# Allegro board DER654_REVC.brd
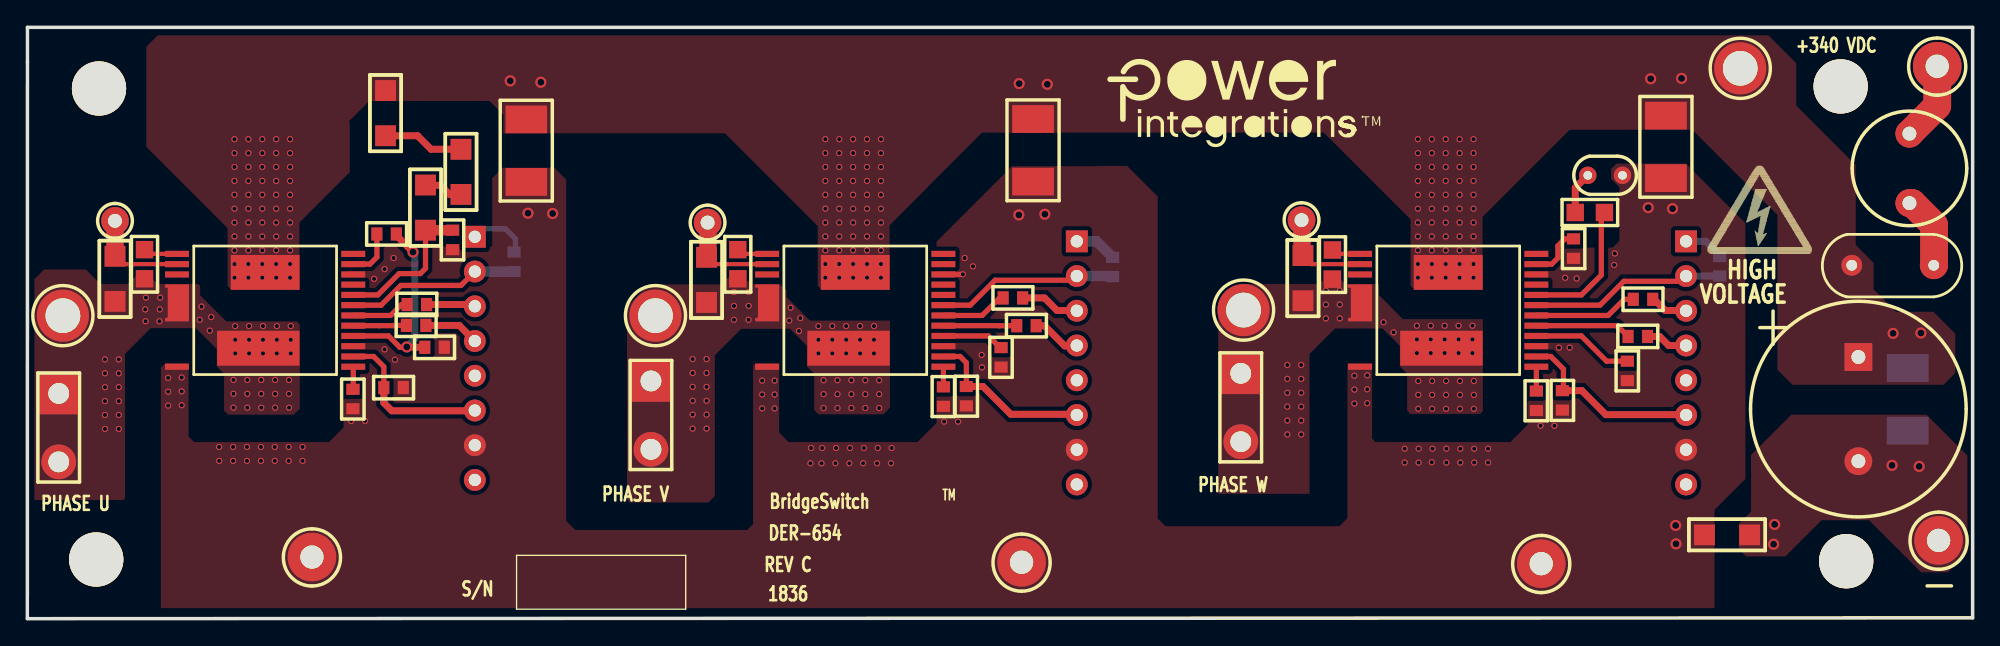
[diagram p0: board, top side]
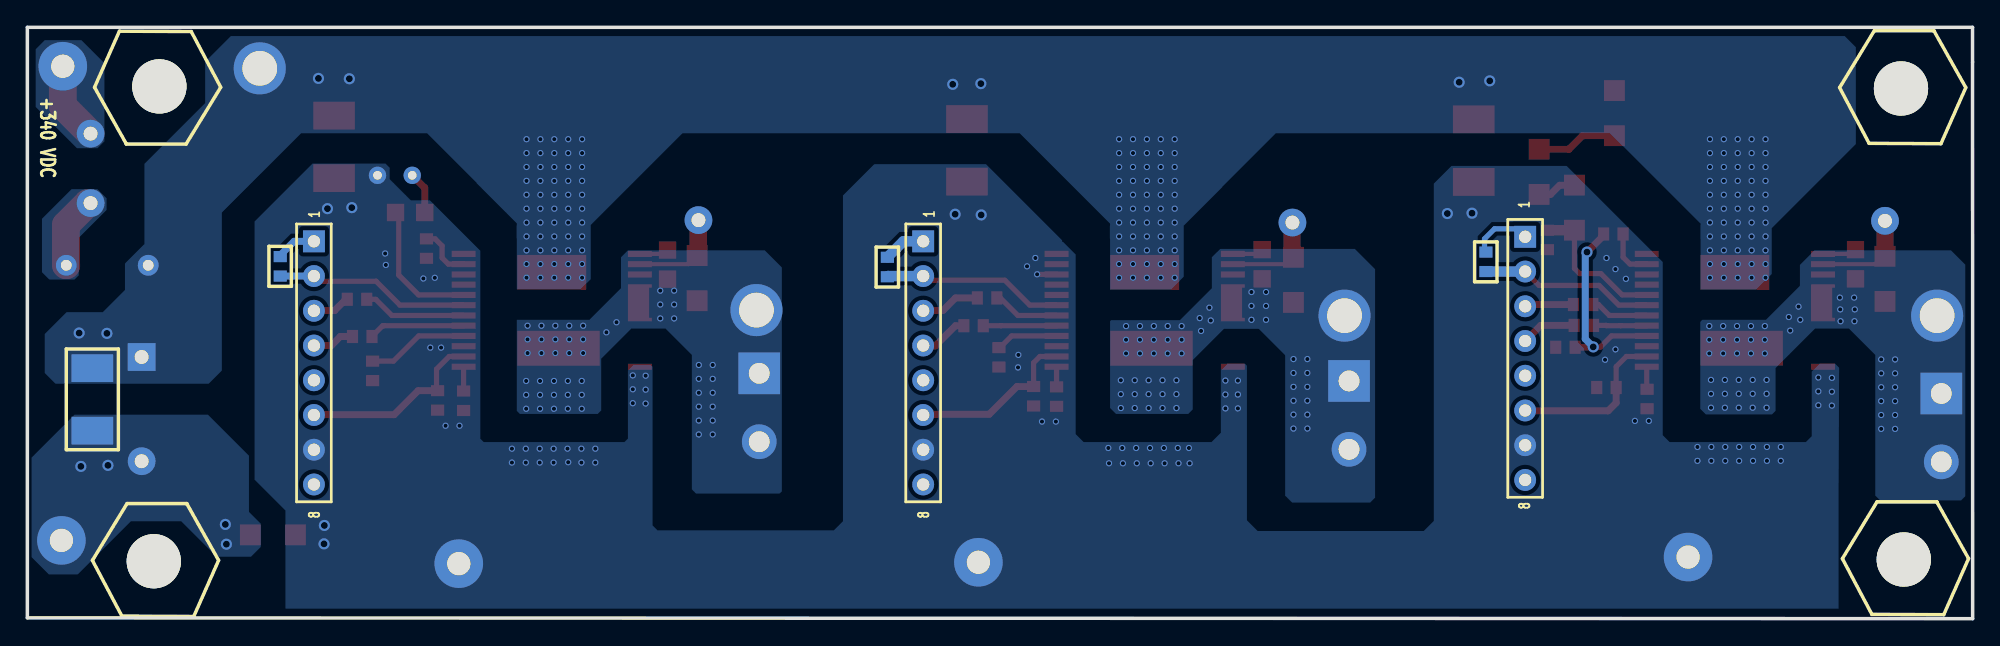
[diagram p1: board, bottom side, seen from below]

Outline 142.25 x 43.24 mm; copper layers: TOP, BOTTOM. Coordinates in mm from the lower left corner of the outline.
Outline path: 0,0 142.25,0.06 142.25,43.24 0.01,43.24 0.01,40.7 0,0

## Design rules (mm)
constraint set DEFAULT: min track width 0.508

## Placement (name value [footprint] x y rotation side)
C1  22 uF  [PIPOLCAPCLYD630LS300040]  133.89 19.13 270 top
C2  220 nF  [PISMC1812]  137.5 18.32 270 bottom
C3  220 nF  [PISMC1812]  36.48 36.51 270 top
C4  4.7 uF  [PISMC1206]  6.41 26.5 270 top
C5  100 pF  [PISMC0603]  31.1 28.4 270 top
C6  1 uF  [PISMC0603]  29.07 19.84 0 top
C7  220 nF  [PISMC1812]  73.54 36.53 270 top
C8  4.7 uF  [PISMC1206]  49.66 26.42 270 top
C9  1 uF  [PISMC0603]  71.2 19.82 270 top
C10  220 nF  [PISMC1812]  119.82 36.79 270 top
C11  4.7 uF  [PISMC1206]  93.28 26.55 270 top
C12  1 uF  [PISMC0603]  117 18.83 270 top
F1  3.15 A  [PI_TR5_SUBMIN_FUSE]  137.62 35.47 270 top
J1  CON8  [HDR1X8]  32.72 27.92 270 top
J2  CON8  [HDR1X8]  76.74 27.59 270 top
J3  CON8  [HDR1X8]  121.29 27.59 270 top
J4  CON2  [PI_CONN_QC_TAB_2PIN_LS200]  2.29 16.47 180 top
J5  CON2  [PI_CONN_QC_TAB_2PIN_LS200]  45.6 17.38 180 top
J6  CON2  [PI_CONN_QC_TAB_2PIN_LS200]  88.73 17.94 180 top
J7  CON1  [PI_KEYSTONE1514-2_POST]  125.25 40.24 0 top
J8  CON1  [PI_KEYSTONE1514-2_POST]  2.6 22.16 0 top
J9  CON1  [PI_KEYSTONE1514-2_POST]  45.93 22.16 0 top
J10  CON1  [PI_KEYSTONE1514-2_POST]  88.93 22.56 0 top
NOREF  -  []  0.01 0.06 90 top
NOREF#2  -  []  -143.92 73.77 0 top
NOREF#3  -  []  78.98 40.9 0 top
NOREF#4  -  []  -244.62 -165.09 0 top
NOREF#5  -  []  0.01 40.7 0 top
POST-CRKT_BRD_6-32_HEX1  Post Hex, 6-32, snap, 0.375L, NYL  [PIMTGHOLED156]  5.04 4.33 180 bottom
POST-CRKT_BRD_6-32_HEX2  Post Hex, 6-32, snap, 0.375L, NYL  [PIMTGHOLED156]  132.6 38.92 0 bottom
POST-CRKT_BRD_6-32_HEX3  Post Hex, 6-32, snap, 0.375L, NYL  [PIMTGHOLED156]  133 4.2 180 bottom
POST-CRKT_BRD_6-32_HEX4  Post Hex, 6-32, snap, 0.375L, NYL  [PIMTGHOLED156]  5.24 38.77 180 bottom
R1  10  [PISMR0603]  29.19 22.97 180 top
R2  10  [PISMR0603]  29.14 21.45 180 top
R3  3 M  [PISMR1206]  26.19 38.62 270 top
R4  2.00 M  [PISMR1206]  31.71 31.02 90 top
R5  2.00 M  [PISMR1206]  29.12 28.4 90 top
R6  10 k  [PISMR0603]  26.07 16.9 0 top
R7  0.0  [PISMR0603]  26.98 28.13 180 top
R8  44.2 k  [PISMR0603]  23.81 16.77 270 top
R9  44.2 k  [PISMR0805]  8.57 26.98 270 top
R10  10  [PISMR0603]  72.78 23.45 180 top
R11  10  [PISMR0603]  73.77 21.42 180 top
R12  10 k  [PISMR0603]  68.66 16.97 270 top
R13  44.2 k  [PISMR0603]  66.99 16.95 270 top
R14  44.2 k  [PISMR0805]  51.95 26.98 270 top
R15  10  [PISMR0603]  118.85 23.35 180 top
R16  10  [PISMR0603]  118.47 20.63 180 top
R17  4.75 k  [PISMR0805]  115.32 29.7 180 top
R18  10 k  [PISMR0603]  112.25 16.67 270 top
R19  0.0  [PISMR0603]  113.06 26.35 90 top
R20  44.2 k  [PISMR0603]  110.35 16.64 270 top
R21  44.2 k  [PISMR0805]  95.44 26.96 270 top
R22  4.7 k  [PISMR0603]  35.59 26.8 270 bottom
R23  4.7 k  [PISMR0603]  79.36 26.42 270 bottom
R24  4.7 k  [PISMR0603]  123.76 26.47 270 bottom
R25  0.0  [PISMR1206]  122.64 6.13 0 top
RT1  2.5  [PI_RAD180X395LS235D031]  139.4 25.84 180 top
RT2  100 k  [PI_RAD_118X118_LS100D025]  116.64 32.42 180 top
TP1  BLK  [PITPKEYSTONE125X125]  20.81 4.5 0 top
TP2  BLK  [PITPKEYSTONE125X125]  72.7 4.12 0 top
TP3  BLK  [PITPKEYSTONE125X125]  110.7 4.02 0 top
TP4  WHT  [PITPKEYSTONE100X100]  6.41 29.09 0 top
TP5  WHT  [PITPKEYSTONE100X100]  49.74 28.96 0 top
TP6  WHT  [PITPKEYSTONE100X100]  93.17 29.14 0 top
TP7  BLK  [PITPKEYSTONE125X125]  139.76 5.72 0 top
TP8  RED  [PITPKEYSTONE125X125]  139.66 40.39 0 top
U1  BRD1265C  [PI_IC_INSOP_24C]  23.83 18.42 180 top
U2  BRD1265C  [PI_IC_INSOP_24C]  66.99 18.42 180 top
U3  BRD1265C  [PI_IC_INSOP_24C]  110.35 18.42 180 top

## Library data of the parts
C1 = CAP POL: room: 1
C2 C3 C7 C10 = CAP NP: room: 1
C4 C8 C11 = CAP NP
C5 = CAP NP: room: 4
C6 C9 C12 = CAP NP: alternate symbols: (pismc0603_1); room: 4
F1 = FUSE: room: 1
J1-J3 = HEADER 8: room: 2
J4-J6 = CON2
J7 = TERM_1Pin: room: 1
J8 J10 = TERM_1Pin: room: 4
J9 = TERM_1Pin
POST-CRKT_BRD_6-32_HEX1-POST-CRKT_BRD_6-32_HEX4 = POST_CRKT_BRD_6-32_HEX
R1 R2 R6 R8-R25 = R
R3-R5 R7 = R: room: 4
RT1 = THERMISTOR: alternate symbols: (pirad550x410ls300040_h)
RT2 = THERMISTOR
TP1 TP7 TP8 = TESTPOINT: room: 4
TP2-TP6 = TESTPOINT
U1-U3 = BridgeSwitch

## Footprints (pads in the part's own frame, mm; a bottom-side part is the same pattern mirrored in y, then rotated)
HDR1X8
  rect 1.6x1.6 hole 0.899: 1(0,0)
  round 1.6 hole 0.899: 2(2.54,0) 3(5.08,0) 4(7.62,0) 5(10.16,0) 6(12.7,0) 7(15.24,0) 8(17.78,0)
PI_CONN_QC_TAB_2PIN_LS200
  rect 3.048x3.048 hole 1.524: 1(0,0)
  round 2.54 hole 1.524: 2(0,5.001)
PI_IC_INSOP_24C
  rect 1.75x0.45 smd: 1(0,0) 2(0,-0.749) 3(0,-1.501) 4(0,-2.25) 5(0,-3) 6(0,-3.749) 7(0,-4.501) 8(0,-5.25) 9(0,-6) 10(0,-6.749) 11(0,-7.501) 12(0,-8.25) 13(12.89,-8.25) 14(12.89,-7.501) 15(12.89,-6.749) 24(12.89,0)
  custom 0.437x0.437 smd: 16(12.89,-4.671)
  rect 6.03x2.555 smd: 19(6.939,-1.349)
  rect 5.039x2.545 smd: 25(6.444,-6.899)
PI_KEYSTONE1514-2_POST
  round 3.81 hole 2.54: 1(0,0)
PI_RAD180X395LS235D031
  round 1.524 hole 0.787: 1(0,0) 2(5.994,0)
PI_RAD_118X118_LS100D025
  round 1.27 hole 0.635: 1(0,0) 2(2.54,0)
PI_TR5_SUBMIN_FUSE
  round 2.032 hole 1.016: 1(0,0) 2(5.08,0)
PIMTGHOLED156
  round 3.962 hole 3.962: 1(0,0)
PIPOLCAPCLYD630LS300040
  rect 2.032x2.032 hole 1.016: 1(0,0)
  round 2.032 hole 1.016: 2(7.62,0)
PISMC0603
  rect 0.813x0.965 smd: 1(0,0) 2(1.422,0)
PISMC1206
  rect 1.524x1.524 smd: 1(0,0) 2(3.302,0)
PISMC1812
  rect 2.032x3.048 smd: 1(0,0) 2(4.572,0)
PISMR0603
  rect 0.813x0.965 smd: 1(0,0) 2(1.422,0)
PISMR0805
  rect 1.27x1.27 smd: 1(0,0) 2(2.134,0)
PISMR1206
  rect 1.524x1.524 smd: 1(0,0) 2(3.302,0)
PITPKEYSTONE100X100
  round 2.032 hole 1.016: 1(0,0)
PITPKEYSTONE125X125
  round 3.556 hole 1.702: 1(0,0)

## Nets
GND: C3.2 C5.2 C6.2 C7.2 C9.2 C10.2 C12.2 J1.7 J2.7 J3.7 R6.2 R8.2 R12.2 R13.2 R18.2 R19.1 R20.2 R25.1 RT2.1 TP1.1 TP2.1 TP3.1 U1.3 U1.10 U1.24 U2.3 U2.10 U2.24 U3.3 U3.10 U3.24
VDD_U: J1.1 R22.1
VDD_V: J2.1 R23.1
VDD_W: J3.1 R24.1
BPH_V: C8.1 TP5.1 U2.14
BPL_V: C9.1 U2.4
BPL_W: C12.1 U3.4
DCNEG: C1.2 C2.2 R25.2 TP7.1
DCPLUS: C1.1 C2.1 C3.1 C7.1 C10.1 J7.1 R3.1 RT1.2 U1.25 U2.25 U3.25
FAULT_U: J1.2 R22.2 U1.7
FAULT_V: J2.2 R23.2 U2.7
FAULT_W: J3.2 R24.2 U3.7
ID_U: R7.2 U1.11
ID_V: U2.11
ID_W: R19.2 U3.11
INH_U: R1.2 U1.6
INH_V: R10.2 U2.6
INH_W: R15.2 U3.6
INL_V: R11.2 U2.5
INL_W: R16.2 U3.5
IPH_U: J1.6 R6.1 U1.2
IPH_V: J2.6 R12.1 U2.2
IPH_W: J3.6 R18.1 U3.2
PHASE U: C4.2 J4.1 J4.2 J8.1 R9.2 U1.16 U1.19
PHASE V: C8.2 J5.1 J5.2 J9.1 R14.2 U2.16 U2.19
PHASE W: C11.2 J6.1 J6.2 J10.1 R21.2 U3.16 U3.19
POWER+: F1.1 TP8.1
PWMH_U: J1.3 R1.1
PWMH_V: J2.3 R10.1
PWMH_W: J3.3 R15.1
PWML_U: J1.4 R2.1
PWML_V: J2.4 R11.1
PWML_W: J3.4 R16.1
SM_U: C5.1 R5.1 U1.8
SM_V: U2.8
SM_W: R17.1 U3.8
XH_U: R9.1 U1.13
XH_V: R14.1 U2.13
XH_W: R21.1 U3.13
XL_U: R8.1 U1.1(XL)
XL_V: R13.1 U2.1(XL)
XL_W: R20.1 U3.1(XL)
N17053801: R3.2 R4.2
N17053803: R4.1 R5.2
N17056296: C4.1 TP4.1 U1.14
N17067195: C11.1 TP6.1 U3.14
N17109437: R17.2 RT2.2
N17176096: F1.2 RT1.1
N17218688: R2.2 U1.5
N17224134: C6.1 R7.1 U1.4

Pads without a net: J1 5 8; J2 5 8; J3 5 8; POST-CRKT_BRD_6-32_HEX1 1; POST-CRKT_BRD_6-32_HEX2 1; POST-CRKT_BRD_6-32_HEX3 1; POST-CRKT_BRD_6-32_HEX4 1; U1 9 12 15; U2 9 12 15; U3 9 12 15

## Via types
v1: diameter 0.813, hole 0.508, TOP to BOTTOM, 22 vias
v2: diameter 0.457, hole 0.305, TOP to BOTTOM, 401 vias

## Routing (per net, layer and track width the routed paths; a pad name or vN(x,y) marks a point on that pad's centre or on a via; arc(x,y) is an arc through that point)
GND: length 1.3
  TOP w0.381: U2.10 68.25,25.17 68.26,25.18
  vias: v1(36.61,29.65) v1(38.41,29.62) v1(72.5,29.52) v1(74.4,29.57) v1(118.52,30.06) v1(120.3,29.98) v1(120.53,6.81) v1(120.56,5.47) v2(10.29,17.61) v2(10.29,16.59) v2(10.29,15.58) v2(11.29,17.64) v2(11.29,16.62) v2(11.29,15.6) v2(14.03,12.56) v2(14.03,11.54) v2(15.04,12.56) v2(15.04,11.54) v2(16.06,12.56) v2(16.06,11.54) v2(17.08,12.56) v2(17.08,11.54) v2(18.09,12.56) v2(18.09,11.54) v2(19.11,12.56) v2(19.11,11.54) v2(20.12,12.56) v2(20.12,11.54) v2(23.68,14.46) v2(24.7,14.46) v2(25.36,24.85) v2(26.12,25.56) v2(26.12,19.69) v2(26.78,26.37) v2(26.88,18.93) v2(53.73,17.41) v2(53.73,16.39) v2(53.73,15.37) v2(54.64,17.41) v2(54.64,16.39) v2(54.64,15.37) v2(57.31,12.48) v2(57.26,11.36) v2(58.12,12.48) v2(58.07,11.36) v2(59.14,12.48) v2(59.09,11.36) v2(60.15,12.48) v2(60.1,11.36) v2(61.12,11.36) v2(61.17,12.48) v2(62.14,11.36) v2(62.19,12.48) v2(63.15,11.36) v2(63.2,12.48) v2(67.04,14.41) v2(68.05,14.41) v2(68.41,25.18) v2(68.54,26.37) v2(69.15,25.76) v2(69.78,19.29) v2(69.81,18.37) v2(97.04,17.76) v2(97.04,16.75) v2(97.04,15.73) v2(97.98,17.79) v2(97.98,16.77) v2(97.98,15.76) v2(100.72,12.43) v2(100.72,11.41) v2(101.73,12.43) v2(101.73,11.41) v2(102.75,12.43) v2(102.7,11.44) v2(103.77,12.43) v2(103.77,11.41) v2(104.78,12.43) v2(104.78,11.41) v2(105.8,12.43) v2(105.8,11.41) v2(106.81,12.43) v2(106.81,11.41) v2(110.65,14.1) v2(111.67,14.1) v2(112,19.82) v2(112.45,24.92) v2(112.78,19.82) v2(113.29,24.87) v2(116.03,25.86) v2(116.09,26.7)
VDD_U: length 4.5
  BOTTOM w0.381: R22.1 35.69,26.91 35.69,27.77 34.96,28.51 33.43,28.51 32.85,27.92 J1.1
VDD_V: length 3.1
  BOTTOM w0.762: R23.1 78.19,27.59 J2.1
VDD_W: length 3
  BOTTOM w0.508: J3.1 122.74,27.59 123.76,26.58 R24.1
BPH_V: length 7.3
  TOP w0.305: C8.1 49.66,26.23 49.97,25.92 U2.14
  TOP w1.27: C8.1 49.77,26.53 49.77,28.94 TP5.1
BPL_V: length 4.6
  TOP w0.381: U2.4 70.27,20.67 71.13,19.82
  TOP w0.508: 71.13,19.82 C9.1
BPL_W: length 7.4
  TOP w0.381: C12.1 115.48,18.83 113.63,20.67 U3.4
DCNEG:
  vias: v1(127.69,5.44) v1(127.77,6.89) v1(136.35,11.21) v1(138.34,11.13)
DCPLUS:
  vias: v1(35.31,39.33) v1(37.55,39.23) v1(72.52,39.12) v1(74.58,39.07) v1(118.7,39.48) v1(120.96,39.5) v1(136.43,20.86) v1(138.46,20.89) v2(15.15,35.06) v2(15.15,34.04) v2(15.15,33.03) v2(15.15,32.01) v2(15.15,31) v2(15.15,29.98) v2(15.15,28.96) v2(15.15,27.95) v2(15.15,26.93) v2(15.15,25.93) v2(15.15,24.93) v2(16.16,35.06) v2(16.16,34.04) v2(16.16,33.03) v2(16.16,32.01) v2(16.16,31) v2(16.16,29.98) v2(16.16,28.96) v2(16.16,27.95) v2(16.16,26.93) v2(16.16,25.93) v2(16.16,24.93) v2(17.18,35.06) v2(17.18,34.04) v2(17.18,33.03) v2(17.18,32.01) v2(17.18,31) v2(17.18,29.98) v2(17.18,28.96) v2(17.18,27.95) v2(17.18,26.93) v2(17.18,25.93) v2(17.18,24.93) v2(18.19,35.06) v2(18.19,34.04) v2(18.19,33.03) v2(18.19,32.01) v2(18.19,31) v2(18.19,29.98) v2(18.19,28.96) v2(18.19,27.95) v2(18.19,26.93) v2(18.19,25.93) v2(18.19,24.93) v2(19.21,35.06) v2(19.21,34.04) v2(19.21,33.03) v2(19.21,32.01) v2(19.21,31) v2(19.21,29.98) v2(19.21,28.96) v2(19.21,27.95) v2(19.21,26.93) v2(19.21,25.93) v2(19.21,24.93) v2(58.35,35.06) v2(58.35,34.04) v2(58.35,33.03) v2(58.35,32.01) v2(58.35,31) v2(58.35,29.98) v2(58.35,28.96) v2(58.35,27.95) v2(58.35,26.93) v2(58.35,25.93) v2(58.35,24.93) v2(59.37,35.06) v2(59.37,34.04) v2(59.37,33.03) v2(59.37,32.01) v2(59.37,31) v2(59.37,29.98) v2(59.37,28.96) v2(59.37,27.95) v2(59.37,26.93) v2(59.37,25.93) v2(59.37,24.93) v2(60.38,35.06) v2(60.38,34.04) v2(60.38,33.03) v2(60.38,32.01) v2(60.38,31) v2(60.38,29.98) v2(60.38,28.96) v2(60.38,27.95) v2(60.38,26.93) v2(60.38,25.93) v2(60.38,24.93) v2(61.4,35.06) v2(61.4,34.04) v2(61.4,33.03) v2(61.4,32.01) v2(61.4,31) v2(61.4,29.98) v2(61.4,28.96) v2(61.4,27.95) v2(61.4,26.93) v2(61.4,25.93) v2(61.4,24.93) v2(62.42,35.06) v2(62.42,34.04) v2(62.42,33.03) v2(62.42,32.01) v2(62.42,31) v2(62.42,29.98) v2(62.42,28.96) v2(62.42,27.95) v2(62.42,26.93) v2(62.42,25.93) v2(62.42,24.93) v2(101.68,35.06) v2(101.68,34.04) v2(101.68,33.03) v2(101.68,32.01) v2(101.68,31) v2(101.68,29.98) v2(101.68,28.96) v2(101.68,27.95) v2(101.68,26.93) v2(101.68,25.93) v2(101.68,24.93) v2(102.7,35.06) v2(102.7,34.04) v2(102.7,33.03) v2(102.7,32.01) v2(102.7,31) v2(102.7,29.98) v2(102.7,28.96) v2(102.7,27.95) v2(102.7,26.93) v2(102.7,25.93) v2(102.7,24.93) v2(103.72,35.06) v2(103.72,34.04) v2(103.72,33.03) v2(103.72,32.01) v2(103.72,31) v2(103.72,29.98) v2(103.72,28.96) v2(103.72,27.95) v2(103.72,26.93) v2(103.72,25.93) v2(103.72,24.93) v2(104.73,35.06) v2(104.73,34.04) v2(104.73,33.03) v2(104.73,32.01) v2(104.73,31) v2(104.73,29.98) v2(104.73,28.96) v2(104.73,27.95) v2(104.73,26.93) v2(104.73,25.93) v2(104.73,24.93) v2(105.75,35.06) v2(105.75,34.04) v2(105.75,33.03) v2(105.75,32.01) v2(105.75,31) v2(105.75,29.98) v2(105.75,28.96) v2(105.75,27.95) v2(105.75,26.93) v2(105.75,25.93) v2(105.75,24.93)
FAULT_U: length 12.8
  TOP w0.381: J1.2 31.71,24.37 27.31,24.37 25.87,22.92 U1.7
  BOTTOM w0.762: R22.2 J1.2
FAULT_V: length 13.3
  TOP w0.381: U2.7 68.95,22.92 70.77,24.75 76.44,24.75 J2.2
  BOTTOM w0.762: J2.2 79.31,25.05 R23.2
FAULT_W: length 14.3
  TOP w0.381: J3.2 120.91,24.67 116.75,24.67 115,22.92 U3.7
  BOTTOM w0.508: R24.2 J3.2
ID_U: length 3.6
  TOP w0.381: U1.11 25.05,25.92 25.56,26.43 R7.2
ID_W: length 4
  TOP w0.381: U3.11 111.46,25.92 111.92,26.38 111.92,27.26 112.43,27.77 R19.2
INH_U: length 4.3
  TOP w0.381: R1.2 27.36,22.97 26.57,22.17 U1.6
INH_V: length 4.9
  TOP w0.381: U2.6 69.82,22.17 71.1,23.45 R10.2
INH_W: length 7.6
  TOP w0.381: R15.2 116.77,23.35 115.59,22.17 U3.6
INL_V: length 5.4
  TOP w0.381: U2.5 71.05,21.42 71.06,21.42 R11.2
INL_W: length 7
  TOP w0.381: U3.5 116.18,21.42 116.19,21.42 116.26,21.42 R16.2
IPH_U: length 12.1
  TOP w0.381: R6.1 26.07,18.42 25.32,19.17 U1.2
  TOP w0.508: J1.6 32.7,15.2 26.65,15.2 26.07,15.78 R6.1
IPH_V: length 12.5
  TOP w0.381: U2.2 68.21,19.17 68.66,18.71 R12.1
  TOP w0.508: J2.6 76.69,14.94 71.91,14.94 69.88,16.97 R12.1
IPH_W: length 13.8
  TOP w0.381: U3.2 111.4,19.17 112.33,18.24 112.33,16.75 R18.1
  TOP w0.508: J3.6 121.27,14.92 115.43,14.92 113.67,16.67 R18.1
PHASE U:
  vias: v2(5.67,18.96) v2(5.67,17.94) v2(5.67,16.92) v2(5.67,15.91) v2(5.67,14.89) v2(5.67,13.88) v2(6.69,18.96) v2(6.69,17.94) v2(6.69,16.92) v2(6.69,15.91) v2(6.69,14.89) v2(6.69,13.88) v2(8.62,22.61) v2(8.64,21.75) v2(8.67,23.48) v2(9.71,23.48) v2(9.68,22.61) v2(9.66,21.75) v2(12.61,21.85) v2(12.73,22.82) v2(13.34,21.06) v2(13.44,22.05) v2(15.07,17.46) v2(15.07,16.44) v2(15.07,15.43) v2(15.2,21.39) v2(15.2,20.39) v2(15.2,19.39) v2(16.09,17.46) v2(16.09,16.44) v2(16.09,15.43) v2(16.21,21.39) v2(16.21,20.39) v2(16.21,19.39) v2(17.1,17.46) v2(17.1,16.44) v2(17.1,15.43) v2(17.23,21.39) v2(17.23,20.39) v2(17.23,19.39) v2(18.12,17.46) v2(18.12,16.44) v2(18.12,15.43) v2(18.24,21.39) v2(18.24,20.39) v2(18.24,19.39) v2(19.13,17.46) v2(19.13,16.44) v2(19.13,15.43) v2(19.26,21.39) v2(19.26,20.39) v2(19.26,19.39)
PHASE V:
  vias: v2(48.65,18.98) v2(48.65,17.97) v2(48.65,16.95) v2(48.65,15.93) v2(48.65,14.92) v2(48.65,13.9) v2(49.66,18.98) v2(49.66,17.97) v2(49.66,16.95) v2(49.66,15.93) v2(49.66,14.92) v2(49.66,13.9) v2(51.67,23.88) v2(51.67,22.87) v2(51.67,21.85) v2(52.74,23.88) v2(52.74,22.87) v2(52.74,21.85) v2(55.71,21.8) v2(55.81,22.74) v2(56.42,21.04) v2(56.52,21.98) v2(57.84,21.39) v2(57.84,20.39) v2(57.84,19.39) v2(58.22,17.43) v2(58.22,16.42) v2(58.22,15.4) v2(58.86,21.39) v2(58.86,20.39) v2(58.86,19.39) v2(59.24,17.43) v2(59.24,16.42) v2(59.24,15.4) v2(59.88,21.39) v2(59.88,20.39) v2(59.88,19.39) v2(60.26,17.43) v2(60.26,16.42) v2(60.26,15.4) v2(60.89,21.39) v2(60.89,20.39) v2(60.89,19.39) v2(61.27,17.43) v2(61.27,16.42) v2(61.27,15.4) v2(61.91,21.39) v2(61.91,20.39) v2(61.91,19.39) v2(62.29,17.43) v2(62.29,16.42) v2(62.29,15.4)
PHASE W:
  vias: v2(92.13,18.55) v2(92.13,17.53) v2(92.13,16.52) v2(92.13,15.5) v2(92.13,14.49) v2(92.13,13.47) v2(93.15,18.55) v2(93.15,17.53) v2(93.15,16.52) v2(93.15,15.5) v2(93.15,14.49) v2(93.15,13.47) v2(94.95,23.99) v2(94.95,22.97) v2(94.95,21.95) v2(95.97,23.99) v2(95.97,22.97) v2(95.97,21.95) v2(99.17,21.67) v2(99.91,20.94) v2(101.61,21.42) v2(101.61,20.42) v2(101.61,19.42) v2(101.71,17.38) v2(101.71,16.37) v2(101.71,15.35) v2(102.62,21.42) v2(102.62,20.42) v2(102.62,19.42) v2(102.73,17.38) v2(102.73,16.37) v2(102.73,15.35) v2(103.64,21.42) v2(103.64,20.42) v2(103.64,19.42) v2(103.74,17.38) v2(103.74,16.37) v2(103.74,15.35) v2(104.66,21.42) v2(104.66,20.42) v2(104.66,19.42) v2(104.76,17.38) v2(104.76,16.37) v2(104.76,15.35) v2(105.67,21.42) v2(105.67,20.42) v2(105.67,19.42) v2(105.77,17.38) v2(105.77,16.37) v2(105.77,15.35)
POWER+: length 5.8
  TOP w2.032: F1.1 139.66,37.5 TP8.1
PWMH_U: length 3.6
  TOP w0.508: R1.1 32.6,22.97 J1.3
PWMH_V: length 4.4
  TOP w0.508: R10.1 74.38,23.45 75.29,22.54 76.72,22.54 J2.3
PWMH_W: length 2.8
  TOP w0.508: R15.1 118.96,23.35 119.77,22.54 121.27,22.54 J3.3
PWML_U: length 4.1
  TOP w0.508: J1.4 31.58,21.45 R2.1
PWML_V: length 3.6
  TOP w0.508: J2.4 76.72,19.95 75.85,19.95 74.38,21.42 R11.1
PWML_W: length 3.1
  TOP w0.508: R16.1 119.36,20.63 120.02,19.97 J3.4
SM_U: length 10.9
  TOP w0.381: R5.1 29.12,25.61 28.73,25.23 27.19,25.23 25.63,23.67 U1.8
  TOP w0.762: C5.1 R5.1
SM_W: length 10
  TOP w0.381: U3.8 113.64,23.67 115.09,25.13 115.09,29.47 R17.1
XH_U: length 2.5
  TOP w0.305: R9.1 8.88,26.67 U1.13
XH_V: length 2.3
  TOP w0.305: R14.1 52.26,26.67 U2.13
XH_W: length 2.1
  TOP w0.305: U3.13 95.75,26.67 95.46,26.96 R21.1
XL_U: length 1.7
  TOP w0.381: R8.1 23.83,16.8 U1.1
XL_V: length 1.5
  TOP w0.381: R13.1 U2.1
XL_W: length 1.8
  TOP w0.381: R20.1 U3.1
N17053801: length 5.9
  TOP w0.508: R4.2 29.52,34.32 28.53,35.31 R3.2
N17053803: length 2.9
  TOP w0.508: R4.1 30.87,31.02 30.2,31.69 29.13,31.69 R5.2
N17056296: length 7.4
  TOP w0.305: C4.1 6.56,26.5 7.14,25.92 U1.14
  TOP w1.27: TP4.1 C4.1
N17067195: length 7.1
  TOP w0.305: U3.14 93.9,25.92 C11.1
  TOP w1.27: TP6.1 93.2,29.12 93.2,26.63 C11.1
N17109437: length 3.1
  TOP w0.508: R17.2 113.19,31.5 RT2.2
N17176096: length 5.4
  TOP w2.032: F1.2 137.83,30.39 139.43,28.79 139.43,25.86 RT1.1
N17218688: length 3.9
  TOP w0.381: U1.5 25.74,21.42 25.74,21.42 26.78,21.42 26.8,21.45 R2.2
N17224134: length 14.7
  TOP w0.381: 27.77,19.84 27.24,19.84 26.41,20.67 U1.4
  TOP w0.508: v1(28.2,26.8) 26.98,28.02 R7.1 ; v1(27.74,19.87) 27.77,19.84 C6.1 29.04,19.82
  BOTTOM w0.508: v1(28.2,26.8) 28.33,26.68 28.33,20.45 v1(27.74,19.87)

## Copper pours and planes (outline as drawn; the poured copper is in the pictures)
GND on TOP: 9.76,18.35 10.07,18.65 11.77,18.65 11.79,18.63 11.79,13.32 12.2,12.91 22.05,12.91 23.12,13.98 23.12,25.06 23.45,25.39 24.38,25.39 26.19,27.21 33.94,27.21 33.99,27.26 33.99,32.21 34.75,32.98 38.54,32.98 39.4,32.11 39.4,7.14 40.06,6.48 52.64,6.48 53.07,6.92 53.07,18.5 53.22,18.65 54.97,18.65 54.97,13.6 55.66,12.91 65.08,12.91 66.48,14.31 66.48,27.57 72,33.09 78.25,33.09 78.26,33.1 80.42,33.1 82.66,30.87 82.66,7.32 83.22,6.76 95.94,6.76 96.53,7.35 96.53,18.65 98.33,18.65 98.33,13.16 98.58,12.91 108.44,12.91 109.71,14.18 109.7,14.19 109.7,25.65 111.18,27.13 115.93,27.13 116.42,27.62 116.42,31.55 115.81,32.16 115.81,32.88 116.21,33.28 121.27,33.28 125.64,28.91 125.64,10.22 123.38,7.96 123.38,0.77 9.81,0.77 9.76,0.82
GND on BOTTOM: 9.8,9.91 9.76,18.35 10.07,18.65 11.18,18.65 11.77,18.07 11.77,13.34 12.2,12.91 22.16,12.91 22.66,13.42 22.66,26.08 29.69,33.1 38.11,33.1 39.4,31.81 39.4,7.14 40.14,6.41 52.28,6.41 53.07,7.2 53.07,18.5 53.26,18.69 53.26,18.66 53.25,18.65 54.49,18.65 54.97,18.17 54.97,13.6 55.66,12.91 65.01,12.91 65.59,13.49 65.59,26.63 66.52,27.55 66.58,27.55 66.58,27.67 72.14,33.23 80.32,33.23 82.61,30.94 82.61,7.12 83.27,6.46 96.17,6.46 96.53,6.81 96.53,18.42 96.68,18.57 97.9,18.57 98.33,18.14 98.33,13.16 98.58,12.91 108.87,12.91 109.13,13.16 109.13,26.91 112.81,30.59 114.21,30.59 115.76,32.14 115.76,32.93 115.73,32.95 116.06,33.28 121.39,33.28 125.64,29.04 125.64,10.17 123.38,7.91 123.38,0.73 9.8,0.73 9.8,9.9
DCNEG on TOP: 141.87,4.83 140.42,3.39 138.49,3.39 134.68,7.2 131.2,7.2 128.56,4.55 125.69,4.55 125.15,5.09 125.15,6.94 126.04,7.83 126.04,11.97 128.99,14.92 138.87,14.92 141.87,11.92
DCNEG on BOTTOM: 138.79,14.92 141.94,11.77 141.94,4.5 140.67,3.23 138.56,3.23 134.68,7.12 131,7.12 128.4,4.53 125.89,4.53 125.18,5.24 125.18,6.94 126.04,7.81 126.04,11.92 129.04,14.92
DCPLUS on TOP: 121.7,35.8 121.65,35.75 112.78,35.75 106.41,29.37 106.41,24.06 101.43,24.06 101.15,24.34 101.15,29.19 94.8,35.54 69.81,35.54 65.86,31.59 65.86,31.57 63.05,28.76 63.05,24.06 58.07,24.06 57.79,24.34 57.79,28.71 51.01,35.49 34.81,35.49 34.81,36.84 33.79,37.85 25,37.85 23.5,36.35 23.58,36.28 23.58,32.65 19.9,28.96 19.9,24.06 14.92,24.06 14.64,24.34 14.64,28.56 8.69,34.5 8.69,41.82 9.53,42.65 127.31,42.65 129.34,40.62 129.34,37.52 133.7,33.17 133.7,27.33 135.01,26.02 135.01,24.09 136.66,22.44 139.38,22.44 140.98,20.84 140.98,17.97 140.11,17.1 129.06,17.1 127.97,18.19 127.97,29.52
DCPLUS on BOTTOM: 128.99,17.18 128.02,18.14 128.02,29.7 122.23,35.49 113.01,35.49 109.41,31.88 109.41,31.86 106.46,28.91 106.46,28.79 106.47,28.77 106.47,27.81 106.46,27.8 106.46,24.09 101.79,24.09 101.05,24.82 101.05,28.79 94.34,35.49 69.68,35.49 63.08,28.89 63.08,28.76 63.09,28.75 63.09,27.78 63.08,27.77 63.08,24.06 58.63,24.06 57.69,25 57.69,28.73 54.87,31.55 54.87,31.58 50.96,35.49 26.5,35.49 19.9,28.89 19.9,28.76 19.91,28.75 19.91,27.78 19.9,27.77 19.9,24.06 15.83,24.06 14.69,25.2 14.69,28.56 8.54,34.7 8.54,41.79 9.35,42.6 127.36,42.6 129.24,40.72 129.24,37.7 133.69,33.26 133.69,27.39 135.11,25.97 135.11,24.04 136.74,22.41 139.38,22.41 140.98,20.81 140.98,17.97 140.19,17.18
PHASE U on TOP: 13.85,18.45 14.38,17.91 14.38,15.22 14.69,14.92 19.49,14.92 19.92,15.35 19.92,21.52 19.71,21.74 14.55,21.74 12.63,23.65 12.63,24.34 12.5,24.47 9.48,24.47 9.48,24.49 9.2,24.77 9.2,25.43 9.18,25.46 7.98,25.46 7.93,25.41 7.93,25.03 7.37,24.47 5.34,24.47 4.27,25.53 1.23,25.53 0.52,24.82 0.52,8.69 0.54,8.67 7.02,8.67 7.14,8.8 7.14,19.36 9.02,21.24 12.33,21.24 13.85,19.72
PHASE U on BOTTOM: 19.92,15.35 19.5,14.93 14.68,14.93 14.41,15.2 14.41,18.32 11.51,21.22 9.05,21.22 7.12,19.29 7.12,9 6.76,8.64 0.85,8.64 0.54,8.95 0.54,25.89 1.58,26.93 11.56,26.93 12.63,25.86 12.63,24.34 15.12,21.85 19.77,21.85 19.92,21.7
PHASE V on TOP: 57.54,17.91 57.54,15.25 57.84,14.94 62.59,14.94 63.08,15.43 63.08,21.75 63.02,21.8 57.23,21.8 55.51,23.53 55.51,23.99 55.05,24.44 52.92,24.44 52.59,24.77 52.59,25.51 51.32,25.51 51.32,25 50.76,24.44 45.45,24.44 43.85,22.84 43.85,8.69 44.05,8.49 49.79,8.49 50.27,8.97 50.27,19.26 52.2,21.19 55.76,21.19 57.01,19.95 57.01,18.45
PHASE V on BOTTOM: 63.08,15.4 62.64,14.97 57.36,14.97 57.03,15.3 57.03,18.91 54.74,21.19 52.2,21.19 50.27,19.26 50.27,9 49.77,8.49 44.05,8.49 43.7,8.85 43.7,25.56 45.17,27.03 55.02,27.03 55.63,26.42 55.63,24.16 57.97,21.83 63,21.83 63.08,21.75
PHASE W on TOP: 96.38,24.47 95.99,24.85 95.99,25.53 94.72,25.53 94.72,24.75 94.44,24.47 88.88,24.47 87.08,22.66 87.08,9.13 93.76,9.13 93.76,19.36 95.61,21.22 99.09,21.22 100.36,19.95 100.36,18.45 100.9,17.91 100.9,15.2 101.12,14.97 106.23,14.97 106.43,15.17 106.43,21.88 106.41,21.9 100.57,21.9 100.57,21.93 98.83,23.67 98.83,24.4 98.76,24.47
PHASE W on BOTTOM: 106.46,15.2 106.23,14.97 100.54,14.97 100.29,15.22 100.29,19.01 98.08,21.22 95.59,21.22 93.66,19.29 93.66,9.46 93.35,9.15 87.23,9.15 87.08,9.3 87.08,25.69 88.32,26.93 98.33,26.93 98.84,26.42 98.84,24.16 101.15,21.85 106.46,21.85
POWER+ on BOTTOM: 136.61,34.91 136.61,40.62 138.29,42.3 140.98,42.3 141.64,41.64 141.64,37.42 138.62,34.4 137.12,34.4
N17176096 on BOTTOM: 137.12,31.4 139.02,31.4 141.18,29.24 141.18,25.33 140.65,24.8 138.79,24.8 138.49,25.1 138.49,27.85 136.46,29.88 136.46,30.74

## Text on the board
Ref Des/Silkscreen Bottom: +340 VDC
Ref Des/Silkscreen Top: TM | PHASE U | S/N | PHASE V | REV C | 1836 | DER-654 | BridgeSwitch | PHASE W | +340 VDC | VOLTAGE | HIGH
User.7: 14. FAB HOUSE LOGO,DATE CODE TO BE IN SILK SCREEN ONLY.DO NOT USE COPPER. | 13   MATERIAL FR4 COPPER 2oz THICKNESS 0.062"
User.9: FIGURE | FINISHED_SIZE | 12.0 | 20.0 | 25.0 | 31.0 | 35.402 | 40.0 | 60.0 | 67.0 | 100.0 | 156.0 | DRILL CHART: TOP to BOTTOM | ALL UNITS ARE IN MILS | PLATED | QTY | 401 | 22 | 2 | 3 | 21 | 7 | 6 | 5 | 4
